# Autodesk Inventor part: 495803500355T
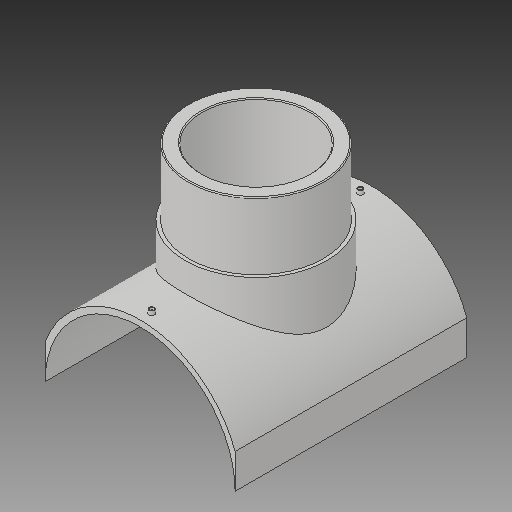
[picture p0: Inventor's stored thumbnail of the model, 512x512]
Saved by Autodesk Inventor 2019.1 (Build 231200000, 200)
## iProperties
Created: 2017-10
Part Number: 495803500355T
Material: Generic
Description: PLASSON BRANCH SADDLE  500x355
Document SubType Name: Modeling
Designer: KIM
Mass: 2754.05 g
Surface Area: 3037.44 cm^2
Volume: 2754.05 cm^3
Density: 1 g/cm^3
Appearance: Default
Author: KIM
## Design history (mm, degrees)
derived "495803.ipt"
feature "Solid1::495803.ipt"
tag "TaggingFeature1"
body "Solid1"
other parameters: "d1" = 16, "d4" = 0, "d12" = 275.6, "d13" = 14, "d14" = 274.5, "d16" = 5 deg, "d18" = 4, "d19" = 14, "d20" = 0, "d21" = 3, "d22" = 0, "d23" = 518, "d24" = 372.75, "d25" = 16, "d26" = 284, "d28" = 0, "d29" = 9.6, "d31" = 0, "d32" = 126, "d33" = 0, "d34" = 5, "d36" = 355, "d37" = 176.4, "d38" = 0, "d39" = 2.5, "d_1" = 355, "H_" = 252, "x_" = 16, "D_" = 16
